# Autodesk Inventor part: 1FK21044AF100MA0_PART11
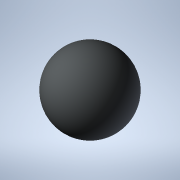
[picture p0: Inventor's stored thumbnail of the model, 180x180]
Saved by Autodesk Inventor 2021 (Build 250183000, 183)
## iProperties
Created: 2025-04
Part Number: 1FK21044AF100MA0_PART11
Material: Generic
Catalog Web Link: www.3dfindit.com
Description: -Servo synchronous motor
Document SubType Name: Modeling
Designer: psAdmin
Mass: 0.137258 g
Surface Area: 1.2868 cm^2
Volume: 0.137258 cm^3
Density: 1 g/cm^3
Appearance: PSOLRGB-212-217-219
Category: PARTsolutions
Title: 1FK21044AF100MA0_PART11
Author: Cadenas PARTsolutions
Comments: Servo synchronous motor
Sending System: PARTsolutions
Preprocessor: ST-DEVELOPER v19.3
PSOL_IDENT_0: {$CADENAS_DATA/23d-libs/siemens_ag/_cat_/ec/e4/1fk21044af100ma0.prj},216 {VTYP=3D},{NB=1FK21044AF100
PSOL_IDENT_1: MA0_PART11},{LINA=1FK21044AF100MA0_PART11},{NN=1FK21044AF100MA0_PART11},{NOPRJ=TRUE},{DATE=19.08.202
PSOL_IDENT_2: 5 14:01:05},{GEOMDATE=30.07.2025 02:01:01},{VERSION=},{LINEID=10},{WBVAR=},{WBNUMERIC=}  {NB=1FK2104
PSOL_IDENT_3: 4AF100MA0_PART11},{LINA=1FK21044AF100MA0_PART11},{KT=DUMMY},{PREVIEW=../../../_pool_/cb/72/p_d211_xx
PSOL_IDENT_4: _00434j.png},{DESCSHORT=SIMOTICS S-1FK2 HD, SINAMICS S210 3AC 400V-480V, 1.27 Nm, 3000 rpm},{DESCLON
PSOL_IDENT_5: G=SIMOTICS S-1FK2 HD servo motor M0=1.27 Nm; PN = 0.4 kW at nN=3000 rpm (380-480 V); PN = 0.2 kW at
PSOL_IDENT_6: nN=1500 rpm (200-240 V); with holding brake; degree of protection IP64; cylindrical shaft D19x40mm;
PSOL_IDENT_7: absolute encoder 22-bit + 12-bit multiturn (encoder AM22DQC); with OCC interface; plug size M17, rot
PSOL_IDENT_8: atable; SIMOTICS S-1FK2 servomotorfor a wide range of uses in industrial environments. SIMOTICS S‑1F
PSOL_IDENT_9: K2 servomotors are compact synchronous motors with a high dynamic performance that set themselves ap
PSOL_IDENT_10: art as a result of their high power density, degree of protection and overload capability. The motor
PSOL_IDENT_11: s are available in two variants: as High Dynamic variant (highest dynamic performance as a result of
PSOL_IDENT_12: the low intrinsic moment of inertia for applications demanding a high dynamic performance with low
PSOL_IDENT_13: moved masses) - and as Compact variant (precise and stable closed-loop control for medium up to larg
PSOL_IDENT_14: e moved masses as a result of a medium intrinsic moment of inertia). SIMOTICSS‑1FK2 servomotors full
PSOL_IDENT_15: y exploit their strengths in a system with the SINAMICSS210 frequency converter and simple connectio
PSOL_IDENT_16: n using the one cable connection (OCC). Advantages include the short control and positioning times,
PSOL_IDENT_17: fast and precise correction of disturbing quantities as well as stable control with a high dynamic p
PSOL_IDENT_18: erformance. The servo motors can be configured to address a wide range of requirements. For example
PSOL_IDENT_19: with and without holding brake, IP64 or IP65 degree of protection, singleturn or multiturn absolute
PSOL_IDENT_20: encoders - to name just a few. Further, the servomotors are available in different shaft heights ext
PSOL_IDENT_21: ending from 20 to 100. A shaft sealing ring is available to achieve an IP65 degree of protection and
PSOL_IDENT_22: for subsequent mounting at the motor or as spare part. SIMOTICS - the optimum motor for each and ev
PSOL_IDENT_23: ery motion control application.},{INTNO=195125043275},{SUPPLIERALTNO=1FK2104-4AF10-0MA0},{MANUID=1FK
PSOL_IDENT_24: 21044AF100MA0},{MANUNAME=Siemens},{MANUTYPEDESC=Synchronous motor 1FK2-HD 1.27 NM},{AAU732=SIMOTICS}
PSOL_IDENT_25: ,{AAO057=S-1FK2},{AAU734=SIMOTICS S-1FK2 HD servo motor M0=1.27 Nm; PN = 0.4 kW at nN=3000 rpm (380-
PSOL_IDENT_26: 480 V); PN = 0.2 kW at nN=1500 rpm (200-240 V); with holding brake; degree of protection IP64; cylin
PSOL_IDENT_27: drical shaft D19x40mm; absolute encoder 22-bit + 12-bit multiturn (encoder AM22DQC); with OCC interf
PSOL_IDENT_28: ace; plug size M17, rotatable;},{AAW338=Synchronous motor 1FK2-HD 1.27 NM},{AAO742=SIMOTICS},{AAO663=
PSOL_IDENT_29: 4042948694015},{NOCUPEROU=1},{PRICEQUANTITY=1},{QUANTITYMIN=1},{QUANTITYINT=1},{CTN=85015100},{COO=D
PSOL_IDENT_30: E},{AAO676=1FK2104-4AF10-0MA0},{AAO677=Siemens AG},{ORDERUNIT=C62},{CONTENTUNIT=C62}
NB: 1FK21044AF100MA0_PART11
NT: Servo synchronous motor
NBSYN: $MANUID._PART11
LINA: 1FK21044AF100MA0_PART11
CATALOG: SIEMENS
PREVIEW: ../../../_pool_/cb/72/p_d211_xx_00434j.png
DESCSHORT: SIMOTICS S-1FK2 HD, SINAMICS S210 3AC 400V-480V, 1.27 Nm, 3000 rpm
DESCLONG: SIMOTICS S-1FK2 HD servo motor M0=1.27 Nm; PN = 0.4 kW at nN=3000 rpm (380-480 V); PN = 0.2 kW at nN=1500 rpm (200-240 V); with holding brake; degree of protect
INTNO: 195125043275
SUPPLIERALTNO: 1FK2104-4AF10-0MA0
MANUID: 1FK21044AF100MA0
MANUNAME: Siemens
MANUTYPEDESC: Synchronous motor 1FK2-HD 1.27 NM
AAU732: SIMOTICS
AAO057: S-1FK2
AAU734: SIMOTICS S-1FK2 HD servo motor M0=1.27 Nm; PN = 0.4 kW at nN=3000 rpm (380-480 V); PN = 0.2 kW at nN=1500 rpm (200-240 V); with holding brake; degree of protect
AAW338: Synchronous motor 1FK2-HD 1.27 NM
AAO742: SIMOTICS
AAO663: 4042948694015.0
NOCUPEROU: 1
PRICEQUANTITY: 1
QUANTITYMIN: 1
QUANTITYINT: 1
CTN: 85015100
COO: DE
ARTICLENO: 1FK21044AF100MA0_PART11
BOMINFO: 1FK21044AF100MA0_PART11
CREATOR: CADENAS GmbH
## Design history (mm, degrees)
feature "2025_04_17_15_33_01_0673"
body "Solid1"
